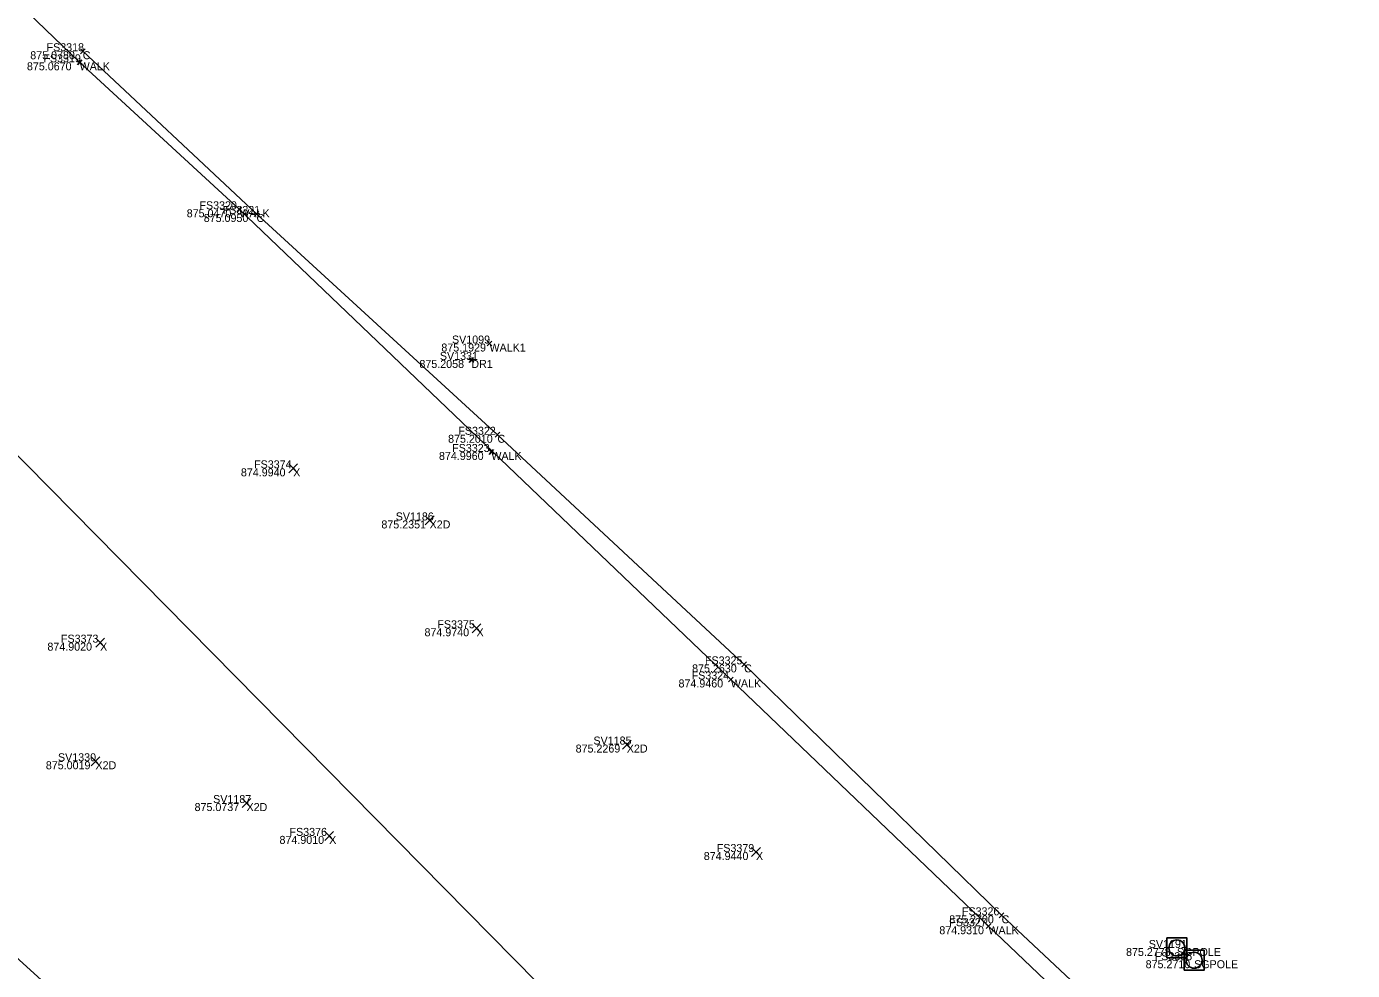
# Model space of a CAD drawing. Extents: x 1479481 to 1575806, y 316056 to 379927.
# Drawn here: x 1480211.87 to 1480221.81, y 379416.34 to 379423.43 of the extents above; entities that cross this region are included whole.
import ezdxf

# ---------------------------------------------------------------- set-up
doc = ezdxf.new("R2010")
doc.units = 0
for name, color, linetype in [('PV_X_Curb', 7, 'Continuous'), ('PV_X_Walk', 7, 'Continuous'), ('SG_X_Poles', 7, 'Continuous'), ('SV_X_Random_Point', 7, 'Continuous'), ('SV_X_Shot_Marker', 7, 'Continuous'), ('SV_X_Text_Comment', 7, 'Continuous'), ('SV_X_Text_Elevation', 7, 'Continuous'), ('SV_X_Text_Name', 7, 'Continuous'), ('UT_X_Water', 7, 'Continuous')]:
    doc.layers.add(name, color=color, linetype=linetype)

msp = doc.modelspace()

# ---------------------------------------------------------------- linework, layer by layer
at = {"layer": 'PV_X_Curb'}
msp.add_lwpolyline([(1480212.291, 379423.24), (1480213.594, 379422.019), (1480215.401, 379420.362), (1480217.251, 379418.639), (1480219.182, 379416.756), (1480220.704, 379415.328), (1480222.514, 379413.605), (1480224.242, 379411.942), (1480225.485, 379410.67)], dxfattribs=at)
at = {"layer": 'PV_X_Walk'}
msp.add_lwpolyline([(1480235.613, 379401.335), (1480225.406, 379410.566), (1480224.081, 379411.883), (1480222.442, 379413.452), (1480220.637, 379415.199), (1480219.083, 379416.674), (1480217.151, 379418.526), (1480213.465, 379422.054), (1480212.267, 379423.157), (1480197.466, 379437.4628), (1480177.803, 379455.9697), (1480154.79, 379476.9674), (1480132.747, 379497.4804), (1480113.376, 379516.7284), (1480110.754, 379519.0396), (1480109.877, 379518.3358), (1480091.944, 379535.2671), (1480093.027, 379536.619), (1480090.219, 379539.2431), (1480090.463, 379539.7253), (1480084.681, 379544.8818), (1480083.843, 379544.144), (1480066.818, 379560.5236), (1480045.662, 379580.0456)], dxfattribs=at)
at = {"layer": 'SG_X_Poles'}
for points in [[(1480220.422, 379416.4359), (1480220.572, 379416.4359), (1480220.572, 379416.5859), (1480220.422, 379416.5859)], [(1480220.551, 379416.344), (1480220.701, 379416.344), (1480220.701, 379416.494), (1480220.551, 379416.494)]]:
    msp.add_lwpolyline(points, close=True, dxfattribs=at)
for centre in [(1480220.497, 379416.5109), (1480220.626, 379416.419)]:
    msp.add_circle(centre, 0.06, dxfattribs=at)
at = {"layer": 'SV_X_Random_Point'}
for p, q in [((1480213.8357, 379420.0766), (1480213.9023, 379420.1434)), ((1480213.8357, 379420.1434), (1480213.9023, 379420.0766)), ((1480214.8587, 379419.6858), (1480214.9253, 379419.7526)), ((1480214.8587, 379419.7526), (1480214.9253, 379419.6858)), ((1480215.2107, 379418.8766), (1480215.2773, 379418.9434)), ((1480215.2107, 379418.9434), (1480215.2773, 379418.8766)), ((1480212.3877, 379418.7686), (1480212.4543, 379418.8354)), ((1480212.3877, 379418.8354), (1480212.4543, 379418.7686)), ((1480216.3377, 379418.004), (1480216.4043, 379418.0708)), ((1480216.3377, 379418.0708), (1480216.4043, 379418.004)), ((1480212.3527, 379417.8786), (1480212.4193, 379417.9454)), ((1480212.3527, 379417.9454), (1480212.4193, 379417.8786)), ((1480213.4857, 379417.5649), (1480213.5523, 379417.6317)), ((1480213.4857, 379417.6317), (1480213.5523, 379417.5649)), ((1480214.1057, 379417.3186), (1480214.1723, 379417.3854)), ((1480214.1057, 379417.3854), (1480214.1723, 379417.3186)), ((1480217.3067, 379417.1976), (1480217.3733, 379417.2644)), ((1480217.3067, 379417.2644), (1480217.3733, 379417.1976))]:
    msp.add_line(p, q, dxfattribs=at)
at = {"layer": 'SV_X_Shot_Marker'}
for p, q in [((1480212.2728, 379423.2571), (1480212.3092, 379423.2229)), ((1480212.3081, 379423.2583), (1480212.2739, 379423.2218)), ((1480212.291, 379423.24), (1480212.291, 379423.24)), ((1480212.2854, 379423.1401), (1480212.2486, 379423.1739)), ((1480212.2501, 379423.1386), (1480212.2839, 379423.1754)), ((1480212.267, 379423.157), (1480212.267, 379423.157)), ((1480213.4831, 379422.0367), (1480213.4469, 379422.0713)), ((1480213.4477, 379422.036), (1480213.4823, 379422.0721)), ((1480213.465, 379422.054), (1480213.465, 379422.054)), ((1480213.5758, 379422.0361), (1480213.6122, 379422.0019)), ((1480213.6111, 379422.0373), (1480213.5769, 379422.0008)), ((1480213.594, 379422.019), (1480213.594, 379422.019)), ((1480215.3589, 379421.0292), (1480215.3231, 379421.064)), ((1480215.3236, 379421.0287), (1480215.3584, 379421.0645)), ((1480215.341, 379421.0466), (1480215.341, 379421.0466)), ((1480215.1867, 379420.9405), (1480215.2233, 379420.9063)), ((1480215.1879, 379420.9052), (1480215.2221, 379420.9417)), ((1480215.205, 379420.9234), (1480215.205, 379420.9234)), ((1480215.3826, 379420.3789), (1480215.4194, 379420.3451)), ((1480215.4179, 379420.3804), (1480215.3841, 379420.3436)), ((1480215.401, 379420.362), (1480215.401, 379420.362)), ((1480215.337, 379420.2504), (1480215.373, 379420.2157)), ((1480215.3723, 379420.251), (1480215.3377, 379420.215)), ((1480215.355, 379420.233), (1480215.355, 379420.233)), ((1480217.2327, 379418.656), (1480217.2693, 379418.622)), ((1480217.268, 379418.6573), (1480217.234, 379418.6207)), ((1480217.251, 379418.639), (1480217.251, 379418.639)), ((1480217.169, 379418.5087), (1480217.133, 379418.5433)), ((1480217.1337, 379418.508), (1480217.1683, 379418.5441)), ((1480217.151, 379418.526), (1480217.151, 379418.526)), ((1480219.1641, 379416.7735), (1480219.1999, 379416.7386)), ((1480219.1995, 379416.7739), (1480219.1645, 379416.7381)), ((1480219.182, 379416.756), (1480219.182, 379416.756)), ((1480219.1011, 379416.6568), (1480219.0649, 379416.6912)), ((1480219.0658, 379416.6559), (1480219.1002, 379416.6921)), ((1480219.083, 379416.674), (1480219.083, 379416.674))]:
    msp.add_line(p, q, dxfattribs=at)
at = {"layer": 'UT_X_Water'}
for points in [[(1480049.152, 379568.0166), (1480068.611, 379550.1932), (1480086.403, 379533.4238), (1480090.024, 379530.0794), (1480102.295, 379519.134), (1480111.734, 379511.4732), (1480120.332, 379509.1362), (1480127.535, 379501.6681), (1480127.911, 379496.3954), (1480140.166, 379484.0843), (1480149.088, 379474.708), (1480164.726, 379459.4824), (1480172.622, 379452.5027), (1480197.813, 379429.1106), (1480212.628, 379415.6841), (1480231.592, 379398.2374)], [(1480224.057, 379407.7701), (1480199.329, 379432.8644)]]:
    msp.add_lwpolyline(points, dxfattribs=at)

# ---------------------------------------------------------------- texts
at = {"layer": 'SV_X_Text_Comment'}
for s, p in [('C', (1480212.291, 379423.18)), ('WALK', (1480212.267, 379423.097)), ('WALK', (1480213.465, 379421.994)), ('C', (1480213.594, 379421.959)), ('WALK1', (1480215.341, 379420.9866)), ('DR1', (1480215.205, 379420.8634)), ('C', (1480215.401, 379420.302)), ('WALK', (1480215.355, 379420.173)), ('X', (1480213.869, 379420.05)), ('X2D', (1480214.892, 379419.6592)), ('X', (1480215.244, 379418.85)), ('X', (1480212.421, 379418.742)), ('C', (1480217.251, 379418.579)), ('WALK', (1480217.151, 379418.466)), ('X2D', (1480216.371, 379417.9774)), ('X2D', (1480212.386, 379417.852)), ('X2D', (1480213.519, 379417.5383)), ('X', (1480214.139, 379417.292)), ('X', (1480217.34, 379417.171)), ('C', (1480219.182, 379416.696)), ('WALK', (1480219.083, 379416.614)), ('SGPOLE', (1480220.497, 379416.4509)), ('SGPOLE', (1480220.626, 379416.359))]:
    msp.add_text(s, height=0.06, dxfattribs=at).set_placement(p)
at = {"layer": 'SV_X_Text_Elevation'}
for s, p in [('875.0780', (1480211.897, 379423.18)), ('875.0670', (1480211.8721, 379423.097)), ('875.0470', (1480213.0705, 379421.994)), ('875.0950', (1480213.1981, 379421.959)), ('875.1929', (1480214.9801, 379420.9866)), ('875.2058', (1480214.8157, 379420.8634)), ('875.2010', (1480215.0307, 379420.302)), ('874.9960', (1480214.9624, 379420.173)), ('874.9940', (1480213.4769, 379420.05)), ('875.2351', (1480214.5305, 379419.6592)), ('874.9740', (1480214.8538, 379418.85)), ('874.9020', (1480212.0256, 379418.742)), ('875.2630', (1480216.8608, 379418.579)), ('874.9460', (1480216.7589, 379418.466)), ('875.2269', (1480215.9874, 379417.9774)), ('875.0019', (1480212.0138, 379417.852)), ('875.0737', (1480213.1293, 379417.5383)), ('874.9010', (1480213.7663, 379417.292)), ('874.9440', (1480216.9484, 379417.171)), ('875.2700', (1480218.789, 379416.696)), ('874.9310', (1480218.715, 379416.614)), ('875.2778', (1480220.1153, 379416.4509)), ('875.2710', (1480220.2623, 379416.359))]:
    msp.add_text(s, height=0.06, dxfattribs=at).set_placement(p)
at = {"layer": 'SV_X_Text_Name'}
for s, p in [('FS3318', (1480212.0194, 379423.24)), ('FS3319', (1480211.9954, 379423.157)), ('FS3320', (1480213.166, 379422.054)), ('FS3321', (1480213.3401, 379422.019)), ('SV1099', (1480215.0599, 379421.0466)), ('SV1331', (1480214.9691, 379420.9234)), ('FS3322', (1480215.1076, 379420.362)), ('FS3323', (1480215.0612, 379420.233)), ('FS3374', (1480213.5756, 379420.11)), ('SV1186', (1480214.6379, 379419.7192)), ('FS3375', (1480214.9502, 379418.91)), ('FS3373', (1480212.1272, 379418.802)), ('FS3325', (1480216.9572, 379418.639)), ('FS3324', (1480216.8576, 379418.526)), ('SV1185', (1480216.1207, 379418.0374)), ('SV1330', (1480212.1049, 379417.912)), ('SV1187', (1480213.2687, 379417.5983)), ('FS3376', (1480213.8414, 379417.352)), ('FS3379', (1480217.0457, 379417.231)), ('FS3327', (1480218.7892, 379416.674)), ('FS3326', (1480218.8844, 379416.756)), ('SV1191', (1480220.2857, 379416.5109)), ('FS3395', (1480220.3303, 379416.419))]:
    msp.add_text(s, height=0.06, dxfattribs=at).set_placement(p)

doc.saveas('drawing.dxf')
